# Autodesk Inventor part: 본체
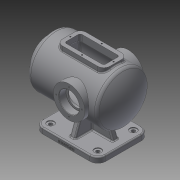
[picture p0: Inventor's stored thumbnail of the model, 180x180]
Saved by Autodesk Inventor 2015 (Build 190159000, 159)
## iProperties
Created: 2021-11
Part Number: 본체
Material: 일반
Document SubType Name: Modeling
Designer: 1019876
Density: 1 g/cm^3
Appearance: 기본값
Author: 1019876
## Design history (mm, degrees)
sketch "스케치1"
  geometry: L1 (80, -65)-(-80, -65); L2 (-80, -65)-(-80, 65); L3 (-80, 65)-(80, 65); L4 (80, 65)-(80, -65); L5 (80, -65)-(-80, 65); L6 (-80, -65)-(80, 65); 1 further point
  constraints: 12 end point, 2 midpoint, 2 parallel, 1 horizontal, 1 perpendicular
  dimensions: "d0" = 130 distance of L3.end L1.start; "d1" = 160 distance of L2.end L3.end
extrude "돌출1" new body sketch "스케치1" distance "d2" = 14; taper "d3" = 0 deg
fillet "모깎기1" dims "d4" = 20
sketch "스케치2"
  geometry: A1 r 20 centre (-60, 45) between (-60, 65) and (-80, 45) reference; A2 r 20 centre (-60, -45) between (-80, -45) and (-60, -65) reference; A3 r 20 centre (60, -45) between (60, -65) and (80, -45) reference; A4 r 20 centre (60, 45) between (80, 45) and (60, 65) reference; 1 further point
hole "구멍1" sketch "스케치2" at (-60, -45), (60, -45), (60, 45), (-60, 45) diameter "d5" = 9; stored, may be unused: countersink angle "d9" = 90 deg, drill point angle "d11" = 118 deg; dims "d6" = 6, "d7" = 18, "d8" = 2, "d10" = 8
sketch "스케치3"
  geometry: L1 (60, -7)-(-60, -7); L2 (-60, -7)-(-60, 7); L3 (-60, 7)-(60, 7); L4 (60, 7)-(60, -7); L5 (60, -7)-(-60, 7); L6 (-60, -7)-(60, 7); L7 (7, -50)-(-7, -50); L8 (-7, -50)-(-7, 50); L9 (-7, 50)-(7, 50); L10 (7, 50)-(7, -50); L11 (7, -50)-(-7, 50); L12 (-7, -50)-(7, 50); 1 further point
  constraints: 24 end point, 4 midpoint, 4 parallel, 2 horizontal, 2 perpendicular
  dimensions: "d12" = 14 distance of L8.end L9.end; "d13" = 14 distance of L1.end L2.end; "d14" = 120 distance of L1.start L1.end; "d15" = 100 distance of L9.end L7.start
extrude "돌출2" join sketch "스케치3" distance "d16" = 100; taper "d17" = 0 deg
feature "면 기울기1" dims angle "d18" = 20 deg
feature "면 기울기2" dims angle "d19" = 20 deg
sketch "스케치6"
  geometry: L1 (100, 114)-(-100, 114); L2 (-75.993, 179)-(100, 179); L3 (100, 179)-(100, 114); L4 (-100, 114)-(100, 179); L5 (80, 14)-(80, 0) reference; L6 (80, 0)-(-80, 0) reference; L7 (-80, 0)-(-80, 14) reference; L8 (-80, 14)-(-60, 14) reference; L9 (-60, 14)-(-23.603, 114) reference; L10 (-23.603, 114)-(23.603, 114) reference; L11 (23.603, 114)-(60, 14) reference; L12 (60, 14)-(80, 14) reference; A1 r 100 centre (0, 114) between (-75.993, 179) and (-100, 114); 5 further points
  constraints: 8 end point, 2 horizontal alignment, 2 midpoint, 2 point on circle, 2 vertical alignment, 1 centre point, 1 horizontal, 1 parallel, 1 point on line
  dimensions: "d28" = 114 distance from line of point (0, 0) L1; "d31" = 65 distance of L2.end L1.start; "d33" = 20 distance between parallel lines of L5 L3; "d35" = 100 radius of A1
revolve "회전1" sketch "스케치6" stored, may be unused: angle "d36" = 90 deg
sketch "스케치8"
  geometry: L1 (80, 14)-(80, 0) reference; L2 (80, 0)-(-80, 0) reference; L3 (-80, 0)-(-80, 14) reference; L4 (-80, 14)-(-60, 14) reference; L5 (-60, 14)-(-47.261, 49) reference; L6 (-47.261, 49)-(-75.993, 49) reference; L7 (-75.993, 179)-(100, 179) reference; L8 (100, 179)-(100, 49) reference; L9 (100, 49)-(47.261, 49) reference; L10 (47.261, 49)-(60, 14) reference; L11 (60, 14)-(80, 14) reference; L12 (-71.239, 169)-(85, 169); L13 (85, 169)-(85, 114); L14 (85, 114)-(-90, 114); A1 r 100 centre (0, 114) between (-75.993, 179) and (-75.993, 49) reference; A2 r 90 centre (0, 114) between (-71.239, 169) and (-90, 114); 1 further point
  constraints: 6 end point, 2 point on circle, 1 centre point, 1 horizontal, 1 parallel, 1 perpendicular, 1 point on line
  dimensions: "d40" = 10 radial gap between concentric circles of A1 A2; "d41" = 55 distance of L12.end L13.end; "d42" = 15 distance between parallel lines of L13 L8
revolve "회전2" sketch "스케치8" stored, may be unused: angle "d43" = 90 deg
sketch "스케치9"
  geometry: C1 r 65 at (0, 0) reference; C2 r 47.5 at (0, 0); 1 further point
  constraints: 1 centre point, 1 coincident
  dimensions: "d44" = 95 diameter of C2
extrude "돌출6" join sketch "스케치9" distance "d45" = 10; taper "d46" = 0 deg
sketch "스케치10"
  geometry: C1 r 47.5 at (0, 0) reference; C2 r 32.5 at (0, 0); 1 further point
  constraints: 1 centre point, 1 coincident
  dimensions: "d47" = 65 diameter of C2
extrude "돌출7" cut sketch "스케치10" distance "d48" = 25; taper "d49" = 0 deg
chamfer "모따기1" distance "d50" = 1; stored, may be unused: second distance "d51" = 2, angle "d52" = 45 deg
sketch "스케치12"
  geometry: C1 r 47.5 at (0, 0) reference; 2 further points
  constraints: 1 horizontal alignment
  dimensions: "d53" = 40 distance of C1.centre point (40, 0)
hole "구멍2" sketch "스케치12" at (40, 0) diameter "d54" = 3.242; stored, may be unused: countersink angle "d58" = 90 deg, drill point angle "d60" = 118 deg; dims "d55" = 11, "d56" = 4, "d57" = 2, "d59" = 13
node "작업 평면2"
sketch "스케치14"
  geometry: L1 (110, 66.5)-(110, 161.5) reference; C1 r 40 at (-17, 114); 1 further point
  constraints: 1 centre point
  dimensions: "d121" = 80 diameter of C1; "d123" = 127 distance from line of L1 C1.centre; "d124" = 114 vertical distance of point (0, 0) C1.centre
extrude "돌출8" join sketch "스케치14" stored distance "d68" = 25; taper "d69" = 0 deg
node "작업 평면3"
sketch "스케치17"
  geometry: L1 (-60, 30)-(60, 30); L2 (60, 30)-(60, -30); L3 (60, -30)-(-60, -30); L4 (-60, -30)-(-60, 30); L5 (-60, 30)-(60, -30); L6 (60, 30)-(-60, -30); L7 (110, -47.5)-(110, 47.5) reference; 2 further points
  constraints: 12 end point, 2 midpoint, 2 parallel, 1 horizontal, 1 perpendicular
  dimensions: "d93" = 120 distance of L2.end L3.end; "d94" = 50 distance between parallel lines of L7 L2; "d96" = 30 distance from line of L3 point (0, 0); "d97" = 30 distance from line of L1 point (0, 0)
extrude "돌출9" join sketch "스케치17" stored distance "d98" = 25; taper "d99" = 0 deg
sketch "스케치18"
  geometry: L1 (60, 30)-(-60, 30) reference; L2 (-60, 30)-(-60, -30) reference; L3 (-60, -30)-(60, -30) reference; L4 (60, -30)-(60, 30) reference; L5 (-50, 20)-(50, 20); L6 (50, 20)-(50, -20); L7 (50, -20)-(-50, -20); L8 (-50, -20)-(-50, 20); 1 further point
  constraints: 8 end point, 3 other
  dimensions: "d100" = 10 distance between parallel lines of L1 L5
extrude "돌출10" cut sketch "스케치18" distance "d101" = 60; taper "d102" = 0 deg
fillet "모깎기3" dims "d103" = 15
fillet "모깎기4" dims "d104" = 5
sketch "스케치19"
  geometry: 2 further points
  constraints: 1 vertical alignment
  dimensions: "d105" = 25 distance of point (0, 0) point (0, 25)
hole "구멍5" sketch "스케치19" at (0, 25) diameter "d106" = 3.242; stored, may be unused: countersink angle "d110" = 90 deg, drill point angle "d112" = 118 deg; dims "d107" = 9, "d108" = 52, "d109" = 18, "d111" = 11
sketch "스케치20"
  geometry: 2 further points
  constraints: 1 horizontal alignment
  dimensions: "d113" = 55 distance of point (0, 0) point (-55, 0)
hole "구멍6" sketch "스케치20" at (-55, 0) diameter "d114" = 3.242; stored, may be unused: countersink angle "d118" = 90 deg, drill point angle "d120" = 118 deg; dims "d115" = 9, "d116" = 52, "d117" = 18, "d119" = 11
sketch "스케치23"
  geometry: C1 r 40 at (0, 0) reference; 1 further point
hole "구멍7" sketch "스케치23" at (0, 0) diameter "d125" = 42; stored, may be unused: countersink angle "d129" = 90 deg, drill point angle "d131" = 0 deg; dims "d126" = 9, "d127" = 52, "d128" = 18, "d130" = 75
sketch "스케치24"
  geometry: C1 r 26 at (0, 0) reference; 2 further points
  constraints: 1 horizontal alignment
  dimensions: "d132" = 32.5 distance of C1.centre point (32.5, 0)
hole "구멍8" sketch "스케치24" at (32.5, 0) diameter "d133" = 3.242; stored, may be unused: countersink angle "d137" = 90 deg, drill point angle "d139" = 118 deg; dims "d134" = 11, "d135" = 52, "d136" = 18, "d138" = 13
chamfer "모따기3" distance "d143" = 1; stored, may be unused: second distance "d144" = 2, angle "d145" = 45 deg
fillet "모깎기5" dims "d146" = 0.3
sketch "스케치25" dims "d15" = 100
  geometry: L1 (120, 0)-(0, 0) reference; 3 further points
  constraints: 1 midpoint, 1 vertical alignment, 1 other
  dimensions: "d147" = 5 distance of point (60, 0) point (60, 5)
feature "엠보싱1" sketch "스케치25" dims "d148" = 0.5, "d149" = 0
fillet "모깎기6" dims "d150" = 3
fillet "모깎기7" dims "d151" = 3
fillet "모깎기8" dims "d152" = 3
fillet "모깎기9" dims "d153" = 3
fillet "모깎기10" dims "d154" = 10
fillet "모깎기11" dims "d155" = 3
fillet "모깎기12" dims "d156" = 3
node "솔리드1"
pattern_circular "원형 패턴1" dims angle "d62" = 360 deg
mirror "대칭2"
mirror "대칭3"
pattern_circular "원형 패턴3" dims angle "d141" = 360 deg
mirror "대칭4"
node "절단 모서리 투영1"
node "절단 모서리 투영2"
other parameters: "d65" = -75, "d92" = -184
